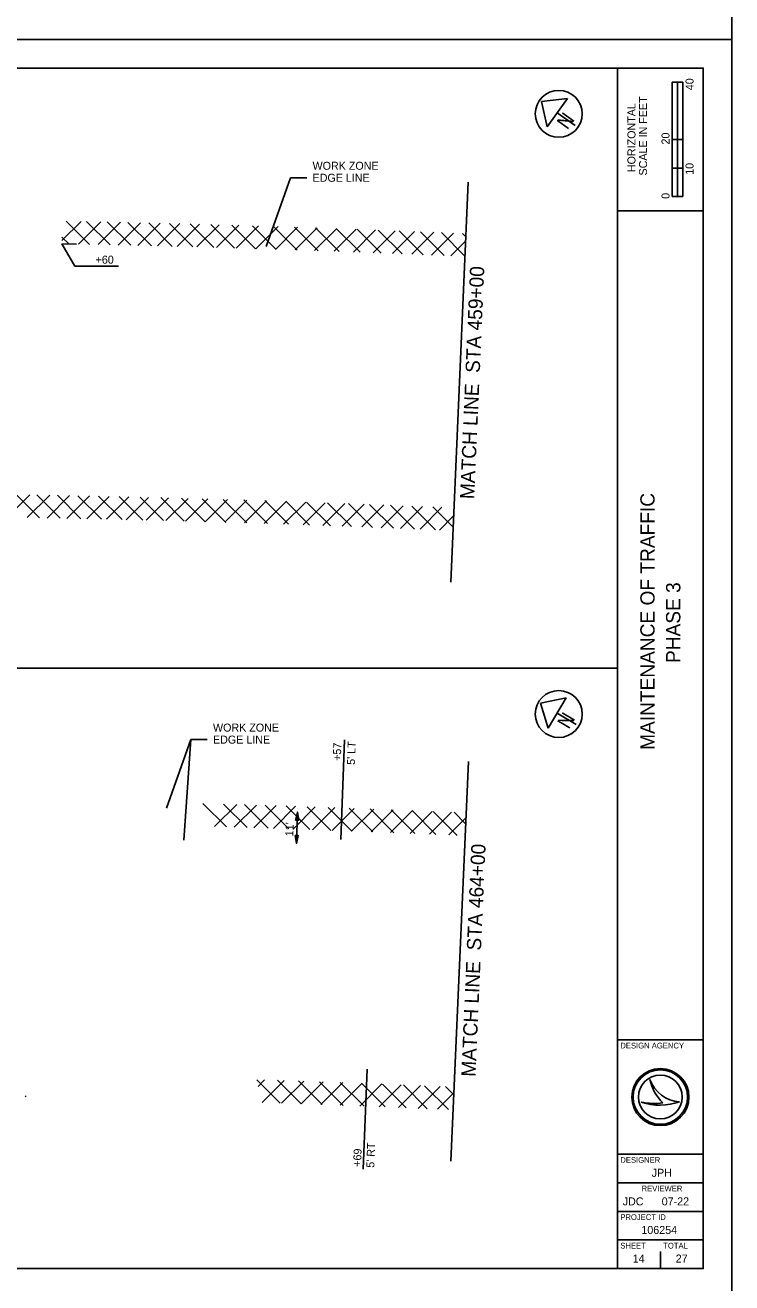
# Model space of a CAD drawing. Extents: x 0 to 5770, y -1320 to 440.
# Drawn here: x 2741.9 to 2989.1, y -435 to 5 of the extents above; entities that cross this region are included whole.
import ezdxf

# ---------------------------------------------------------------- set-up
doc = ezdxf.new("R2010")
doc.units = 0
for name, color, linetype in [('_CIVIL_CONSTRUCTION', 7, 'Continuous'), ('GE_P_Alignment', 7, 'Continuous'), ('GE_P_Alignment_100_Bearings', 7, 'Continuous'), ('GE_P_Alignment_100_Cardinal_Points', 7, 'Continuous'), ('GE_P_Alignment_100_Curve_Data', 7, 'Continuous'), ('GE_P_Alignment_100_Distances', 7, 'Continuous'), ('GE_P_Alignment_100_Stations', 7, 'Continuous'), ('HY_X_Water_Edge', 7, 'Continuous'), ('RD_X_GR_Rt', 7, 'Continuous')]:
    doc.layers.add(name, color=color, linetype=linetype)

msp = doc.modelspace()

# ---------------------------------------------------------------- linework, layer by layer
at = {"layer": '_CIVIL_CONSTRUCTION'}
for points in [[(2309.06, 0), (2989.06, 0), (2989.06, 440), (2309.06, 440)], [(2309.06, -440), (2989.06, -440), (2989.06, 0), (2309.06, 0)]]:
    msp.add_lwpolyline(points, close=True, dxfattribs=at)
at = {"layer": 'GE_P_Alignment'}
for p, q in [((2949.06, -430), (2949.06, -10)), ((2949.06, -60), (2979.06, -60)), ((2949.06, -350), (2979.06, -350)), ((2949.06, -390), (2979.06, -390)), ((2949.06, -400), (2979.06, -400)), ((2949.06, -410), (2979.06, -410)), ((2949.06, -420), (2979.06, -420))]:
    msp.add_line(p, q, dxfattribs=at)
msp.add_lwpolyline([(2339.06, -10), (2979.06, -10), (2979.06, -430), (2339.06, -430)], close=True, dxfattribs=at)
at = {"layer": 'GE_P_Alignment_100_Bearings'}
for p, q in [((2968.2, -55), (2968.2, -15)), ((2971.95, -15), (2968.2, -15)), ((2968.2, -35), (2968.2, -15)), ((2968.2, -15), (2970.06, -15)), ((2970.06, -15), (2970.08, -15)), ((2970.08, -15), (2970.08, -35)), ((2971.95, -15), (2971.95, -55)), ((2970.08, -35), (2968.2, -35)), ((2971.93, -35), (2970.06, -35)), ((2970.06, -35), (2970.06, -45)), ((2971.93, -45), (2971.93, -35)), ((2970.06, -45), (2968.2, -45)), ((2968.2, -45), (2968.2, -55)), ((2970.06, -55), (2970.06, -45)), ((2970.06, -45), (2971.93, -45)), ((2971.95, -55), (2968.2, -55)), ((2968.2, -55), (2970.06, -55)), ((2960.41, -363.81), (2960.41, -363.81)), ((2957.41, -371.81), (2957.41, -371.81)), ((2964.06, -370), (2964.06, -370)), ((2970.81, -371.63), (2970.81, -371.63)), ((2956.56, -426.5), (2956.56, -426.5)), ((2964.06, -430), (2964.06, -424))]:
    msp.add_line(p, q, dxfattribs=at)
for radius in [10, 9.54, 9.54, 7.64]:
    msp.add_circle((2964.06, -370), radius, dxfattribs=at)
for centre, radius, start, end in [((2971.38, -360.05), 11.6, 198.9257, 198.9319), ((2976, -360.6), 15.91, 191.6379, 191.6421), ((2971.38, -360.05), 11.6, 198.9319, 267.1657), ((2976, -360.6), 15.91, 191.6421, 226.0947), ((2963.85, -352.6), 20.26, 251.4576, 290.0832), ((2962.02, -346.91), 25.32, 259.4964, 259.4995), ((2963.85, -352.6), 20.26, 251.4527, 251.4576), ((2962.02, -346.91), 25.32, 259.4995, 276.6672)]:
    msp.add_arc(centre, radius, start, end, dxfattribs=at)
at = {"layer": 'GE_P_Alignment_100_Cardinal_Points'}
for p, q in [((2931.58, -20.63), (2922.45, -21.66)), ((2922.45, -21.66), (2924.42, -30.63)), ((2924.42, -30.63), (2931.58, -20.63)), ((2928, -25.63), (2934.29, -30.13)), ((2339.06, -220), (2949.06, -220)), ((2931.1, -230.38), (2922.1, -232.21)), ((2922.1, -232.21), (2924.84, -240.98)), ((2924.84, -240.98), (2931.1, -230.38)), ((2927.97, -235.68), (2934.63, -239.62))]:
    msp.add_line(p, q, dxfattribs=at)
for centre in [(2928.53, -26.01), (2928.53, -236.01)]:
    msp.add_circle(centre, 8.2, dxfattribs=at)
at = {"layer": 'GE_P_Alignment_100_Curve_Data'}
for p, q in [((2834.71, -48.39), (2826.15, -72.38)), ((2840.41, -48.39), (2834.71, -48.39)), ((2890.74, -189.83), (2896.85, -49.96)), ((2754.71, -71.51), (2759.25, -79.32)), ((2759.25, -79.32), (2774.51, -79.32)), ((2799.89, -244.95), (2791.33, -268.95)), ((2799.89, -244.95), (2797.44, -280.11)), ((2805.6, -244.95), (2799.89, -244.95)), ((2852.35, -279.89), (2853.61, -245.02)), ((2890.8, -392.46), (2896.91, -252.59)), ((2837.13, -270.3), (2836.76, -281.29)), ((2861.48, -360.2), (2860.14, -395.2))]:
    msp.add_line(p, q, dxfattribs=at)
at = {"layer": 'GE_P_Alignment_100_Distances'}
for points in [[(2837.6, -273.12), (2836.48, -273.08), (2837.13, -270.3)], [(2836.3, -278.48), (2837.42, -278.51), (2836.76, -281.29)]]:
    msp.add_lwpolyline(points, close=True, dxfattribs=at)
at = {"layer": 'GE_P_Alignment_100_Stations'}
for p, q in [((2761.44, -63.64), (2754.73, -70.35)), ((2756.2, -63.53), (2764.36, -71.7)), ((2768.37, -63.78), (2760.53, -71.62)), ((2763.41, -63.68), (2771.59, -71.86)), ((2775.29, -63.94), (2767.46, -71.77)), ((2770.64, -63.83), (2778.82, -72.02)), ((2782.2, -64.1), (2774.38, -71.92)), ((2777.87, -64), (2786.07, -72.19)), ((2789.1, -64.27), (2781.29, -72.08)), ((2785.11, -64.17), (2793.32, -72.38)), ((2795.99, -64.44), (2788.19, -72.25)), ((2792.37, -64.35), (2800.59, -72.57)), ((2802.88, -64.63), (2795.08, -72.42)), ((2799.63, -64.54), (2807.86, -72.77)), ((2809.76, -64.82), (2801.97, -72.61)), ((2806.9, -64.74), (2815.14, -72.98)), ((2816.63, -65.02), (2808.85, -72.8)), ((2814.18, -64.95), (2822.43, -73.2)), ((2823.49, -65.23), (2815.72, -73)), ((2821.47, -65.17), (2829.74, -73.44)), ((2830.34, -65.45), (2822.58, -73.21)), ((2828.77, -65.4), (2837.05, -73.68)), ((2837.19, -65.68), (2829.44, -73.43)), ((2836.08, -65.64), (2844.37, -73.92)), ((2844.03, -65.91), (2836.28, -73.65)), ((2843.4, -65.89), (2851.7, -74.18)), ((2754.76, -69.17), (2757.14, -71.55)), ((2850.86, -66.15), (2843.12, -73.88)), ((2857.68, -66.4), (2849.95, -74.12)), ((2850.73, -66.14), (2859.04, -74.45)), ((2864.49, -66.65), (2856.78, -74.37)), ((2858.07, -66.41), (2866.39, -74.73)), ((2871.3, -66.92), (2863.59, -74.63)), ((2865.42, -66.69), (2873.75, -75.02)), ((2878.1, -67.19), (2870.4, -74.89)), ((2872.77, -66.98), (2881.12, -75.32)), ((2884.89, -67.47), (2877.2, -75.16)), ((2880.14, -67.27), (2888.5, -75.63)), ((2891.68, -67.76), (2883.99, -75.44)), ((2887.52, -67.58), (2895.72, -75.78)), ((2894.91, -67.9), (2896.02, -69.01)), ((2895.95, -70.55), (2890.78, -75.72)), ((2743.55, -159.32), (2735.68, -167.18)), ((2738.76, -159.23), (2746.9, -167.38)), ((2750.49, -159.44), (2742.63, -167.3)), ((2745.95, -159.36), (2754.11, -167.51)), ((2757.43, -159.58), (2749.58, -167.43)), ((2753.16, -159.49), (2761.32, -167.66)), ((2764.36, -159.72), (2756.52, -167.56)), ((2760.37, -159.64), (2768.55, -167.81)), ((2771.28, -159.87), (2763.45, -167.7)), ((2767.6, -159.79), (2775.78, -167.98)), ((2778.19, -160.03), (2770.37, -167.85)), ((2774.83, -159.95), (2783.03, -168.15)), ((2785.09, -160.2), (2777.28, -168.01)), ((2782.07, -160.12), (2790.28, -168.33)), ((2791.99, -160.37), (2784.18, -168.18)), ((2789.33, -160.3), (2797.54, -168.52)), ((2798.88, -160.56), (2791.08, -168.35)), ((2796.59, -160.49), (2804.82, -168.72)), ((2805.75, -160.75), (2797.97, -168.53)), ((2803.86, -160.69), (2812.1, -168.94)), ((2812.63, -160.95), (2804.85, -168.73)), ((2811.14, -160.9), (2819.39, -169.16)), ((2819.49, -161.16), (2811.72, -168.92)), ((2818.43, -161.12), (2826.69, -169.39)), ((2826.34, -161.37), (2818.58, -169.13)), ((2833.19, -161.6), (2825.44, -169.35)), ((2825.73, -161.35), (2834, -169.63)), ((2840.03, -161.83), (2832.29, -169.57)), ((2833.04, -161.59), (2841.33, -169.88)), ((2846.86, -162.07), (2839.13, -169.8)), ((2840.36, -161.84), (2848.66, -170.14)), ((2853.68, -162.32), (2845.96, -170.04)), ((2847.69, -162.1), (2856, -170.41)), ((2860.5, -162.57), (2852.78, -170.29)), ((2855.03, -162.36), (2863.35, -170.69)), ((2862.38, -162.64), (2870.71, -170.98)), ((2867.31, -162.83), (2859.6, -170.54)), ((2874.11, -163.11), (2866.41, -170.81)), ((2869.73, -162.93), (2878.08, -171.28)), ((2880.9, -163.39), (2873.21, -171.08)), ((2877.1, -163.23), (2885.46, -171.58)), ((2887.68, -163.67), (2880, -171.36)), ((2884.48, -163.54), (2891.58, -170.63)), ((2891.75, -166.67), (2886.78, -171.64)), ((2891.87, -163.85), (2891.88, -163.86)), ((2804.03, -267.29), (2812.27, -275.52)), ((2815.93, -267.63), (2808.15, -275.4)), ((2811.31, -267.49), (2819.56, -275.74)), ((2822.79, -267.84), (2815.02, -275.6)), ((2818.6, -267.71), (2826.86, -275.97)), ((2829.65, -268.05), (2821.89, -275.81)), ((2825.89, -267.93), (2834.16, -276.2)), ((2836.49, -268.28), (2828.74, -276.03)), ((2833.2, -268.17), (2841.48, -276.45)), ((2843.33, -268.51), (2835.59, -276.25)), ((2840.51, -268.41), (2848.81, -276.7)), ((2850.16, -268.75), (2842.43, -276.48)), ((2847.84, -268.67), (2856.14, -276.97)), ((2856.99, -269), (2849.26, -276.72)), ((2855.17, -268.93), (2863.49, -277.24)), ((2863.8, -269.25), (2856.09, -276.97)), ((2862.52, -269.2), (2870.84, -277.53)), ((2870.61, -269.51), (2862.9, -277.22)), ((2877.41, -269.78), (2869.71, -277.49)), ((2869.87, -269.49), (2878.21, -277.82)), ((2884.2, -270.06), (2876.51, -277.76)), ((2877.24, -269.78), (2885.59, -278.13)), ((2890.99, -270.35), (2883.31, -278.03)), ((2884.61, -270.08), (2892.97, -278.44)), ((2896.04, -272.37), (2890.09, -278.32)), ((2891.99, -270.39), (2895.96, -274.36)), ((2822.95, -363.98), (2831.12, -372.16)), ((2825.65, -363.97), (2823.36, -366.27)), ((2832.5, -364.2), (2824.75, -371.95)), ((2830.16, -364.12), (2838.44, -372.4)), ((2839.34, -364.43), (2831.59, -372.17)), ((2837.47, -364.36), (2845.76, -372.66)), ((2846.17, -364.67), (2838.43, -372.4)), ((2844.8, -364.62), (2853.1, -372.92)), ((2852.99, -364.91), (2845.27, -372.64)), ((2859.81, -365.17), (2852.09, -372.89)), ((2852.13, -364.88), (2860.45, -373.2)), ((2859.48, -365.16), (2867.8, -373.48)), ((2866.62, -365.43), (2858.91, -373.14)), ((2873.42, -365.7), (2865.72, -373.4)), ((2866.83, -365.44), (2875.17, -373.78)), ((2880.21, -365.98), (2872.52, -373.67)), ((2874.2, -365.73), (2882.55, -374.09)), ((2887, -366.27), (2879.31, -373.95)), ((2881.57, -366.04), (2889.93, -374.4)), ((2891.85, -368.49), (2886.1, -374.24)), ((2888.96, -366.35), (2891.82, -369.21)), ((2742.21, -369.63), (2741.93, -369.91))]:
    msp.add_line(p, q, dxfattribs=at)
at = {"layer": 'HY_X_Water_Edge'}
for centre in [(2928.53, -26.01), (2928.53, -236.01)]:
    msp.add_circle(centre, 8.2, dxfattribs=at)
at = {"layer": 'RD_X_GR_Rt'}
msp.add_line((2759.85, -71.61), (2754.71, -71.51), dxfattribs=at)

# ---------------------------------------------------------------- texts
at = {"layer": 'GE_P_Alignment_100_Bearings'}
for s, height, rotation, p in [('40', 2.8, 90, (2975.67, -17.75)), ('SCALE IN FEET', 2.8, 90, (2959.41, -47.59)), ('HORIZONTAL', 2.8, 90, (2955.36, -46.42)), ('20', 2.8, 90, (2967.27, -36.75)), ('10', 2.8, 90, (2975.67, -47.35)), ('0', 2.8, 90, (2967.27, -55.77)), ('MATCH LINE  STA 459+00', 5, 87.5, (2898.96, -160.91)), ('MAINTENANCE OF TRAFFIC', 5, 90, (2962.06, -248.55)), ('PHASE 3', 5, 90, (2971.06, -218.15)), ('MATCH LINE  STA 464+00', 5, 87.5, (2899.41, -362.99))]:
    msp.add_text(s, height=height, rotation=rotation, dxfattribs=at).set_placement(p)
for s, height, p in [('DESIGN AGENCY', 2, (2950.06, -353)), ('DESIGNER', 2, (2950.06, -393)), ('JPH', 2.8, (2961.03, -397.9)), ('REVIEWER', 2, (2957.5, -403)), ('JDC', 2.8, (2950.89, -407.9)), ('07-22', 2.8, (2964.54, -407.9)), ('PROJECT ID', 2, (2950.06, -413)), ('106254', 2.8, (2957.42, -417.9)), ('SHEET', 2, (2950.06, -423)), ('TOTAL', 2, (2965.06, -423)), ('14', 2.8, (2954.39, -427.9)), ('27', 2.8, (2969.43, -427.9))]:
    msp.add_text(s, height=height, dxfattribs=at).set_placement(p)
at = {"layer": 'GE_P_Alignment_100_Cardinal_Points'}
for rotation, p in [(54.4056, (2931.51, -31.86)), (59.4056, (2932.01, -241.58))]:
    msp.add_text('N', height=5, rotation=rotation, dxfattribs=at).set_placement(p)
at = {"layer": 'GE_P_Alignment_100_Curve_Data'}
for s, p in [('WORK ZONE', (2842.42, -45.59)), ('EDGE LINE', (2842.42, -49.79)), ('+60', (2766.54, -78.44)), ('WORK ZONE', (2807.6, -242.15)), ('EDGE LINE', (2807.6, -246.35))]:
    msp.add_text(s, height=2.8, dxfattribs=at).set_placement(p)
for s, rotation, p in [('+57', 87.9302, (2852.29, -252.43)), ("5' LT", 87.9302, (2857.23, -253.82)), ("11'", 88.0844, (2835.66, -278.81)), ("5' RT", 87.8091, (2864, -394.77)), ('+69', 87.8091, (2859.37, -394.43))]:
    msp.add_text(s, height=2.8, rotation=rotation, dxfattribs=at).set_placement(p)

doc.saveas('drawing.dxf')
